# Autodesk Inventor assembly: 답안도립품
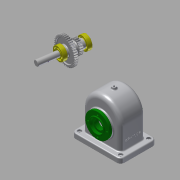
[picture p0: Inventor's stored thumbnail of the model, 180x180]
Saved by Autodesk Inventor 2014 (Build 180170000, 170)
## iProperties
Created: 2016-10
Part Number: 답안도립품
Document SubType Name: Assembly
Designer: SCD-A13
Author: SCD-A13
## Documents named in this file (9)
- C:\Users\SCD-A13\Desktop\461007V1010\답안도립품.iam
- C:\Users\SCD-A13\Desktop\461007V1010\본체.ipt
- C:\Users\SCD-A13\Desktop\461007V1010\축.ipt
- C:\Users\SCD-A13\Desktop\461007V1010\키 - 5 x 5 x 18.ipt
- C:\Users\SCD-A13\Desktop\461007V1010\키 - 6 x 6 x 22.ipt
- C:\Users\SCD-A13\Desktop\461007V1010\베어링 6203.ipt
- C:\Users\SCD-A13\Desktop\461007V1010\스퍼기어.ipt
- C:\Users\SCD-A13\Desktop\461007V1010\뒤커버.ipt
- C:\Users\SCD-A13\Desktop\461007V1010\앞커버.ipt
